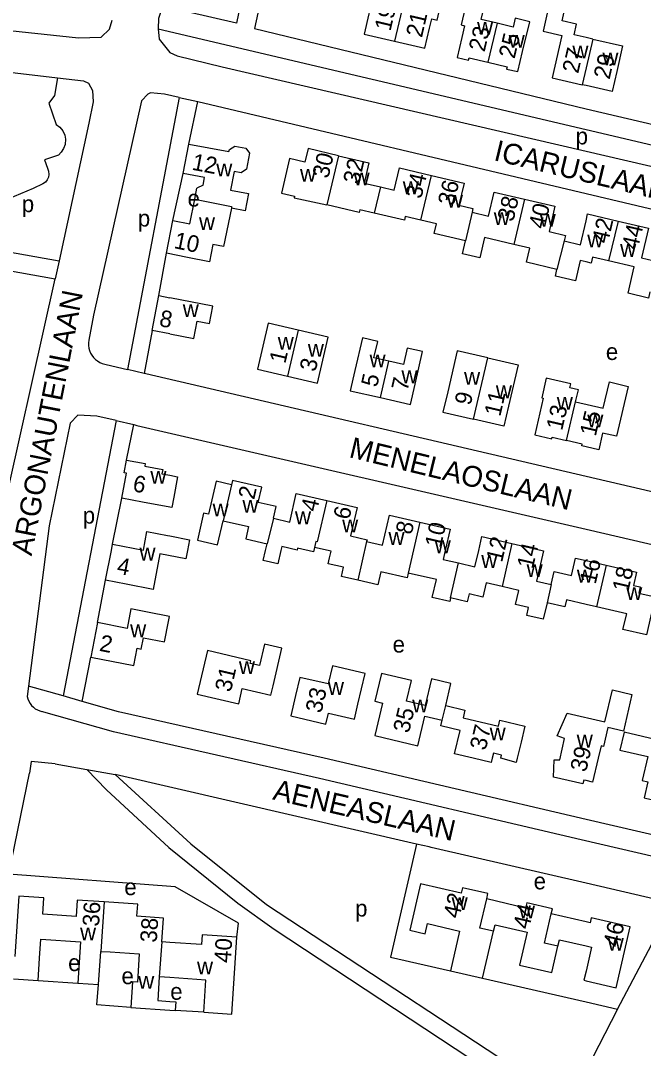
# Model space of a CAD drawing. Extents: x 161773 to 163836, y 384796 to 386521.
# Drawn here: x 162464.1 to 162613.8, y 385630.2 to 385877.5 of the extents above; entities that cross this region are included whole.
import ezdxf

# ---------------------------------------------------------------- set-up
doc = ezdxf.new("R2010")
doc.units = 0
for name, color, linetype in [('BLT_Basislijn', 7, 'Continuous'), ('BLT_Bebouwing', 7, 'Continuous'), ('BLT_Centroide', 7, 'Continuous'), ('BLT_Huisnummer', 7, 'Continuous'), ('BLT_Huisnummer_ tussenligend', 7, 'Continuous'), ('BLT_Onderverdeling_panden', 7, 'Continuous'), ('BLT_Straatnaam', 7, 'Continuous')]:
    doc.layers.add(name, color=color, linetype=linetype)

msp = doc.modelspace()

# ---------------------------------------------------------------- linework, layer by layer
at = {"layer": 'BLT_Basislijn'}
for p, q in [((162461.42, 385865.06), (162472.97, 385863.71)), ((162502.23, 385858.98), (162489.78, 385793.51)), ((162502.23, 385858.98), (162506.71, 385857.98)), ((162504.5, 385847.76), (162506.71, 385857.98)), ((162500.72, 385829.35), (162503.15, 385840.66)), ((162414.31, 385825.68), (162472.4, 385815.29)), ((162497.32, 385811.31), (162499.13, 385821.48)), ((162473.35, 385819.69), (162472.4, 385815.29)), ((162451.9, 385723.59), (162472.4, 385815.29)), ((162495.7, 385802.91), (162493.82, 385792.55)), ((162484.66, 385794.72), (162489.78, 385793.51)), ((162493.82, 385792.55), (162489.78, 385793.51)), ((162487.07, 385781.24), (162474.31, 385715)), ((162487.07, 385781.24), (162491.31, 385780.26)), ((162489.56, 385771.74), (162491.31, 385780.26)), ((162486.21, 385751.53), (162488.44, 385762.56)), ((162482.6, 385732.63), (162484.53, 385742.82)), ((162478.88, 385713.69), (162480.99, 385724.31)), ((162466.02, 385717.38), (162465.7, 385714.88)), ((162474.31, 385715), (162466.02, 385717.38)), ((162478.88, 385713.69), (162474.31, 385715)), ((162466.61, 385699.21), (162466.25, 385696.44)), ((162472.41, 385698.7), (162466.61, 385699.21)), ((162472.41, 385698.7), (162480.03, 385697.29)), ((162480.03, 385697.29), (162486.81, 385696.07)), ((162461.27, 385672.1), (162466.25, 385696.44)), ((162559.29, 385679.37), (162486.81, 385696.07)), ((162560.79, 385679.02), (162559.29, 385679.37)), ((162562.34, 385678.67), (162560.79, 385679.02)), ((162468.3, 385646.56), (162477.83, 385645.91)), ((162508.14, 385638.94), (162501.24, 385639.38))]:
    msp.add_line(p, q, dxfattribs=at)
for points in [[(162529.37, 385941.22), (162515.97, 385876.86), (162498.2, 385880.88)], [(162312.67, 385896.24), (162312.77, 385894.67), (162313.69, 385892.54), (162317.19, 385890.56), (162477.99, 385873.28), (162483.44, 385873.42), (162485.48, 385875.36), (162486.1, 385877.57)], [(162498.2, 385880.88), (162497.24, 385877.94), (162497.15, 385875.44)], [(162521.74, 385882.16), (162520.32, 385875.52), (162600, 385856.24), (162711.04, 385830.23)], [(162497.15, 385875.44), (162497.39, 385872.99), (162499.99, 385869.75), (162501.74, 385869), (162512.55, 385866.3), (162600, 385846.01), (162705.04, 385821.65), (162706.25, 385821.76), (162708.69, 385825.93)], [(162497.15, 385875.44), (162600, 385851.25), (162686.26, 385830.96), (162708.69, 385825.93)], [(162425.24, 385869.19), (162421.12, 385828.99), (162473.35, 385819.69)], [(162472.97, 385863.71), (162472.22, 385859.43), (162470.92, 385857.59), (162472.66, 385852.48), (162473.55, 385851.82), (162474.24, 385850.96), (162474.71, 385849.92), (162474.9, 385848.93), (162474.8, 385847.64), (162474.44, 385846.64), (162473.85, 385845.76), (162473.17, 385845.11), (162469.82, 385843.97), (162470.52, 385841.91), (162470.8, 385841.23), (162470.89, 385840.42), (162470.78, 385839.8), (162470.48, 385839.13), (162470.05, 385838.6), (162469.42, 385838.16), (162467.14, 385837.07), (162459.5, 385833.85)], [(162472.97, 385863.71), (162479.21, 385862.98), (162480.38, 385862.38), (162481.41, 385860.63), (162481.51, 385857.94), (162480.53, 385852.8), (162473.35, 385819.69)], [(162502.23, 385858.98), (162498.71, 385859.75), (162495.28, 385860.05), (162494.64, 385859.77), (162493.14, 385858.11), (162481.65, 385806.62), (162480.46, 385800.6)], [(162506.71, 385857.98), (162600, 385835.85), (162640.95, 385826.14), (162696.67, 385813.29), (162698.68, 385810.91), (162698.59, 385809.21), (162697.98, 385807.33), (162695.51, 385802.74), (162670.9, 385757.98), (162668.34, 385753.87), (162666.97, 385753.1), (162663.98, 385752.9), (162600, 385767.81), (162494.17, 385792.47), (162493.82, 385792.55)], [(162480.46, 385800.6), (162480.4, 385799.96), (162480.41, 385799.32), (162480.5, 385798.69), (162480.68, 385798.07), (162480.93, 385797.48), (162481.24, 385796.93), (162481.63, 385796.42), (162482.08, 385795.96), (162482.58, 385795.57), (162483.12, 385795.23), (162483.71, 385794.97), (162484.32, 385794.79), (162484.66, 385794.72)], [(162487.07, 385781.24), (162482.43, 385782.28), (162477.87, 385782.53), (162476.02, 385780.59), (162470.93, 385755.93), (162466.02, 385717.38)], [(162491.31, 385780.26), (162492.03, 385780.09), (162600, 385755.09), (162650.39, 385743.43), (162656.88, 385741.42), (162658.73, 385739.77), (162658.98, 385738.52), (162658.89, 385736.42), (162645.84, 385711.4), (162639.64, 385700), (162630.76, 385683.64)], [(162465.7, 385714.88), (162465.85, 385714.29), (162466.07, 385713.73), (162466.37, 385713.21), (162466.73, 385712.73), (162467.16, 385712.3), (162467.63, 385711.94), (162468.15, 385711.64), (162468.71, 385711.41), (162469.09, 385711.3)], [(162627.38, 385678.91), (162600, 385685.3), (162537.03, 385700), (162487.65, 385711.18), (162478.88, 385713.69)], [(162621.27, 385675.2), (162598.86, 385680.43), (162535.91, 385695.13), (162486.41, 385706.33), (162469.09, 385711.3)], [(162480.03, 385697.29), (162484.76, 385692.41), (162499.73, 385678.57), (162516.28, 385665.15), (162525.02, 385658.94), (162593.93, 385613.48)], [(162486.81, 385696.07), (162505.04, 385679.47), (162523.2, 385664.83), (162595.86, 385617.08)], [(162559.29, 385679.37), (162553.03, 385652.18), (162567.4, 385648.92)], [(162607.61, 385639.65), (162618.82, 385660.94), (162619.18, 385663.66), (162617.56, 385665.85), (162600, 385669.93), (162562.75, 385678.57), (162562.34, 385678.67)], [(162516.1, 385656.99), (162516.47, 385660.37), (162501.21, 385669.05), (162461.27, 385672.1)], [(162490.56, 385640.09), (162482.41, 385640.73), (162482.81, 385645.58)], [(162575.15, 385647.11), (162600, 385641.4), (162607.61, 385639.65)], [(162607.61, 385639.65), (162600, 385625.03), (162595.86, 385617.08)]]:
    msp.add_lwpolyline(points, dxfattribs=at)
at = {"layer": 'BLT_Bebouwing'}
for p, q in [((162503.15, 385840.66), (162504.5, 385847.76)), ((162507.94, 385837.89), (162506.48, 385837.1)), ((162499.13, 385821.48), (162500.72, 385829.35)), ((162495.7, 385802.91), (162497.32, 385811.31)), ((162497.32, 385811.31), (162500, 385810.79)), ((162500, 385802.08), (162495.7, 385802.91)), ((162522.98, 385750), (162523.34, 385751.57)), ((162582.21, 385751.67), (162589.45, 385750)), ((162482.6, 385732.63), (162480.99, 385724.31)), ((162560.24, 385669.84), (162557.63, 385658.67)), ((162575.15, 385647.11), (162577.79, 385658.39)), ((162468.66, 385651.94), (162468.97, 385656.5)), ((162482.81, 385645.58), (162483.35, 385653.57)), ((162468.3, 385646.56), (162468.66, 385651.94)), ((162567.4, 385648.92), (162575.15, 385647.11)), ((162462.35, 385646.96), (162468.3, 385646.56)), ((162477.83, 385645.91), (162482.81, 385645.58))]:
    msp.add_line(p, q, dxfattribs=at)
for points in [[(162601.61, 385873.01), (162600, 385873.38), (162597.16, 385874.04), (162597.74, 385876.56), (162594.25, 385877.37), (162597.13, 385890.48), (162593.34, 385891.35)], [(162556.51, 385883.36), (162549.47, 385885.2), (162549.72, 385886.24), (162548.36, 385886.56), (162547.19, 385881.58), (162548.34, 385881.3), (162547.81, 385879.06), (162546.67, 385874.19), (162553.96, 385872.48)], [(162553.96, 385872.48), (162561.24, 385870.78), (162562.38, 385875.64), (162562.91, 385877.88), (162564.19, 385877.58), (162565.67, 385883.91), (162557.01, 385885.94), (162556.51, 385883.36)], [(162578.63, 385876.81), (162574.79, 385877.73), (162575.27, 385879.72), (162575.54, 385880.84), (162571.31, 385881.85), (162570.01, 385876.41), (162570.83, 385876.21), (162570.16, 385873.41), (162569, 385868.55), (162571.75, 385867.89), (162571.89, 385868.48), (162576.39, 385867.41)], [(162591.3, 385882.08), (162589.72, 385874.89), (162594.23, 385873.89), (162591.87, 385863.69), (162599.06, 385862.02)], [(162576.39, 385867.41), (162581.03, 385866.3), (162580.91, 385865.8), (162583.6, 385865.16), (162584.76, 385870.03), (162586.46, 385877.17), (162582.97, 385878), (162582.47, 385875.9), (162578.63, 385876.81)], [(162601.61, 385873.01), (162608.8, 385871.34), (162607.38, 385865.18), (162606.26, 385860.36), (162600, 385861.81), (162599.06, 385862.02)], [(162504.5, 385847.76), (162514.14, 385845.93), (162514.31, 385846.4), (162515.6, 385847.28), (162518.25, 385846.77), (162519.1, 385845.53), (162518.37, 385841.69), (162517.08, 385840.81), (162515.42, 385841.12), (162514.57, 385836.67), (162518.88, 385835.85)], [(162540.49, 385844.93), (162533.2, 385846.64), (162532.43, 385843.38), (162528.73, 385844.25), (162526.79, 385835.96), (162529.96, 385835.22), (162529.87, 385834.85), (162537.71, 385833.09)], [(162540.49, 385844.93), (162547.79, 385843.22), (162546.65, 385838.38), (162550.57, 385837.46)], [(162507.94, 385837.89), (162508.28, 385839.68), (162503.15, 385840.66)], [(162550.57, 385837.46), (162553.9, 385836.68), (162555.16, 385842.02), (162562.84, 385840.21)], [(162562.84, 385840.21), (162570.7, 385838.37), (162569.45, 385833.05), (162572.81, 385832.26), (162572.6, 385831.36)], [(162505.95, 385834.5), (162506.48, 385837.1)], [(162518.88, 385835.85), (162518.1, 385831.72), (162514.75, 385832.36)], [(162572.6, 385831.36), (162576.55, 385830.43), (162577.91, 385836.21), (162585.21, 385834.5)], [(162500.72, 385829.35), (162504.75, 385828.53), (162505.95, 385834.5)], [(162585.21, 385834.5), (162592.54, 385832.78), (162591.11, 385826.72), (162595.08, 385825.79), (162594.77, 385824.44)], [(162514.75, 385832.36), (162512.87, 385823.1), (162510.33, 385823.61), (162509.48, 385819.39), (162504.21, 385820.45), (162499.13, 385821.48)], [(162549.09, 385831.15), (162545.63, 385831.96), (162545.46, 385831.27), (162537.71, 385833.09)], [(162560.31, 385829.41), (162556.54, 385830.29), (162556.35, 385829.44), (162549.09, 385831.15)], [(162594.77, 385824.44), (162598.65, 385823.53), (162600, 385829.29), (162600.39, 385830.95), (162607.7, 385829.23)], [(162571.07, 385824.51), (162563.54, 385826.27), (162564.07, 385828.53), (162560.31, 385829.41)], [(162607.7, 385829.23), (162615, 385827.52), (162613.33, 385820.39), (162617.39, 385819.43)], [(162582.66, 385823.62), (162575.62, 385825.28), (162574.46, 385820.35), (162570.32, 385821.32), (162571.07, 385824.51)], [(162593.01, 385817.59), (162585.67, 385819.31), (162586.48, 385822.73), (162582.66, 385823.62)], [(162605.44, 385819.63), (162601.59, 385820.53), (162601.26, 385819.11), (162600, 385819.4), (162598.61, 385819.73), (162597.46, 385814.84), (162592.63, 385815.97), (162593.01, 385817.59)], [(162615.34, 385812.19), (162615, 385810.71), (162610.12, 385811.86), (162611.61, 385818.18), (162605.44, 385819.63)], [(162500, 385802.08), (162505.75, 385800.96), (162506.56, 385805.15), (162509.52, 385804.58), (162510.33, 385808.79), (162500, 385810.79)], [(162530.81, 385802.96), (162523.57, 385804.65), (162521, 385793.61), (162528.24, 385791.92)], [(162528.24, 385791.92), (162535.47, 385790.24), (162538.04, 385801.27), (162530.81, 385802.96)], [(162552.57, 385795.51), (162549.03, 385796.32), (162549.93, 385800.28), (162546.24, 385801.12), (162544.46, 385793.29), (162543.35, 385788.42), (162550.58, 385786.77)], [(162550.58, 385786.77), (162557.81, 385785.13), (162558.92, 385790.01), (162560.7, 385797.84), (162557.01, 385798.68), (162556.11, 385794.71), (162552.57, 385795.51)], [(162576.39, 385796.34), (162569.06, 385797.98), (162566.76, 385788.15), (162565.62, 385783.28), (162572.95, 385781.57)], [(162576.39, 385796.34), (162583.71, 385794.64), (162581.41, 385784.74), (162580.28, 385779.87), (162572.95, 385781.57)], [(162597.5, 385785.76), (162598.17, 385788.62), (162596.15, 385789.09), (162596.38, 385790.06), (162590.46, 385791.43), (162589.36, 385786.71), (162589.72, 385786.62), (162587.67, 385777.77), (162591.79, 385776.81), (162591.9, 385777.25), (162595.32, 385776.46)], [(162597.5, 385785.76), (162604.16, 385784.21), (162605.63, 385790.52), (162610.15, 385789.47), (162607.35, 385777.46), (162604, 385778.24), (162603.06, 385774.2), (162600, 385774.91), (162598.96, 385775.15), (162599.06, 385775.59), (162595.32, 385776.46)], [(162488.44, 385762.56), (162489.55, 385768.56), (162488.99, 385768.66), (162489.56, 385771.74)], [(162489.56, 385771.74), (162494.04, 385770.92), (162493.93, 385770.28), (162498.26, 385769.48), (162498.06, 385768.43), (162500, 385768.08)], [(162500, 385768.08), (162501.81, 385767.74), (162500.91, 385762.82), (162500.45, 385760.34), (162500, 385760.43)], [(162514.81, 385765.82), (162511.11, 385766.68), (162509.26, 385758.69), (162508.02, 385758.97), (162506.58, 385752.45), (162511.45, 385751.33), (162512.81, 385757.15)], [(162524.85, 385757.74), (162525.5, 385760.54), (162521.2, 385761.53), (162522.05, 385765.18), (162515.03, 385766.8), (162514.81, 385765.82)], [(162500, 385760.43), (162493.36, 385761.65), (162488.44, 385762.56)], [(162524.85, 385757.74), (162528.77, 385756.83), (162530.35, 385763.71), (162537.68, 385762.01)], [(162537.68, 385762.01), (162545, 385760.32), (162543.42, 385753.48), (162547.37, 385752.56), (162547.27, 385752.13)], [(162512.81, 385757.15), (162518.9, 385755.74), (162518.21, 385752.76), (162523.34, 385751.57)], [(162547.27, 385752.13), (162551.12, 385751.24), (162552.78, 385758.47), (162560.06, 385756.79)], [(162560.06, 385756.79), (162567.33, 385755.11), (162566.15, 385750)], [(162486.21, 385751.53), (162493.61, 385750.1), (162494.47, 385754.55), (162499.38, 385753.6), (162500, 385753.48)], [(162484.53, 385742.82), (162485.92, 385750), (162486.21, 385751.53)], [(162500, 385753.48), (162504.68, 385752.58), (162504.18, 385750)], [(162574.2, 385750), (162574.97, 385753.34), (162582.21, 385751.67)], [(162504.18, 385750), (162503.79, 385747.96), (162497.59, 385749.16), (162495.94, 385740.62), (162489.44, 385741.87), (162484.53, 385742.82)], [(162526.68, 385750), (162525.93, 385746.76), (162522.42, 385747.57), (162522.98, 385750)], [(162534.74, 385750.71), (162534.51, 385749.68), (162530.68, 385750.56), (162530.57, 385750.06), (162526.89, 385750.91), (162526.68, 385750)], [(162538.72, 385749.79), (162534.74, 385750.71)], [(162545.14, 385742.86), (162541.23, 385743.76), (162541.74, 385745.95), (162538.03, 385746.8), (162538.36, 385748.25), (162538.72, 385749.79)], [(162566.15, 385750), (162565.65, 385747.84), (162569.38, 385746.98)], [(162569.38, 385746.98), (162573.3, 385746.08), (162574.2, 385750)], [(162589.45, 385750), (162589.77, 385749.92), (162588.09, 385742.63), (162591.65, 385741.81)], [(162591.65, 385741.81), (162592.37, 385744.9), (162596.54, 385743.94), (162597.51, 385748.17), (162600, 385747.6), (162604.82, 385746.48)], [(162557.24, 385744.56), (162556.98, 385743.44), (162550.68, 385744.89), (162549.96, 385741.75), (162545.14, 385742.86)], [(162567.45, 385738.6), (162567.24, 385737.71), (162563.04, 385738.68), (162564.03, 385742.99), (162557.24, 385744.56)], [(162604.82, 385746.48), (162612.13, 385744.8), (162611.39, 385741.6), (162613.03, 385741.23), (162612.69, 385739.76), (162616.63, 385738.85), (162614.52, 385729.71), (162608.87, 385731.02), (162609.8, 385734.73), (162602.5, 385736.42)], [(162579.82, 385741.3), (162575.97, 385742.19), (162575.18, 385738.78), (162571.89, 385739.54), (162571.46, 385737.67), (162567.45, 385738.6)], [(162590.66, 385737.42), (162589.74, 385733.44), (162585.75, 385734.36), (162586.19, 385736.25), (162583.06, 385736.97), (162583.85, 385740.37), (162579.82, 385741.3)], [(162602.5, 385736.42), (162600, 385736.99), (162595.29, 385738.08), (162594.91, 385736.44), (162590.66, 385737.42)], [(162480.99, 385724.31), (162491.35, 385722.31), (162492.15, 385726.47), (162493.11, 385726.28), (162493.63, 385728.99), (162498.71, 385728.01), (162499.66, 385732.92), (162499.89, 385734.14), (162494.6, 385735.16), (162490.58, 385735.94), (162489.67, 385731.26), (162482.6, 385732.63)], [(162524.25, 385715.19), (162524.33, 385715.53), (162524.77, 385717.41), (162526.88, 385726.51), (162522.73, 385727.47), (162521.52, 385722.29), (162519.27, 385722.82), (162519.43, 385723.47), (162508.98, 385725.9), (162506.55, 385715.44), (162516.52, 385713.12), (162517.37, 385716.79), (162524.25, 385715.19)], [(162544.33, 385709.39), (162545.17, 385713.04), (162546.88, 385720.44), (162539.07, 385722.25), (162538.06, 385717.89), (162531.22, 385719.47), (162530.2, 385715.07), (162529.07, 385710.19), (162537.47, 385708.25), (162538.07, 385710.84), (162544.33, 385709.39)], [(162566.28, 385712.71), (162567.52, 385717.99), (162562.84, 385719.09), (162561.34, 385712.68), (162556.86, 385713.73), (162558.04, 385718.75), (162550.84, 385720.44), (162549.26, 385713.71), (162551.07, 385713.28), (162549.23, 385705.46), (162559.55, 385703.04)], [(162604.55, 385708.74), (162606.37, 385716.46), (162611.04, 385715.36), (162608.98, 385706.55), (162605.26, 385707.41), (162604.21, 385702.86), (162603.61, 385703), (162602.92, 385700), (162601.59, 385694.27), (162600, 385694.64), (162599.47, 385694.76), (162599.26, 385693.86), (162592.2, 385695.49), (162592.32, 385699.61), (162593.68, 385699.61), (162594.87, 385704.74), (162593.05, 385705.43), (162595.47, 385710.83), (162604.55, 385708.74)], [(162566.28, 385712.71), (162570.89, 385711.62), (162570.45, 385709.72), (162578.94, 385707.71), (162579.28, 385709.15), (162585.31, 385707.73), (162584.39, 385703.86)], [(162559.55, 385703.04), (162561.22, 385710.17), (162565.45, 385709.17)], [(162584.39, 385703.86), (162583.48, 385700), (162583.24, 385698.99), (162579.55, 385700), (162579.72, 385700.73), (162577.74, 385701.2), (162577.46, 385700), (162577.22, 385698.97), (162572.86, 385700), (162568.4, 385701.05), (162569.73, 385706.7), (162565.12, 385707.78), (162565.45, 385709.17)], [(162621.1, 385698.16), (162621.89, 385701.47), (162617.58, 385702.5), (162617.98, 385704.2), (162609.15, 385706.31), (162608.11, 385701.96), (162614.84, 385700.41), (162613.51, 385694.63), (162614.9, 385694.31), (162613.96, 385690.49), (162625.12, 385687.84), (162627.23, 385696.7), (162621.1, 385698.16)], [(162576.14, 385666.17), (162576.44, 385667.45), (162570.31, 385668.88), (162570, 385667.56), (162560.24, 385669.84)], [(162469.45, 385662.51), (162469.71, 385666.45), (162463.69, 385666.86), (162462.71, 385652.34)], [(162484.15, 385665.48), (162477.7, 385665.92), (162477.44, 385661.97), (162469.45, 385662.51)], [(162498.02, 385655.85), (162498.41, 385661.59), (162492.07, 385662.01), (162492.27, 385664.94), (162484.15, 385665.48)], [(162591.65, 385662.59), (162591.94, 385663.83), (162585.78, 385665.27), (162585.48, 385663.99), (162576.14, 385666.17)], [(162593.25, 385654.78), (162593.63, 385656.36), (162600, 385654.87), (162601.34, 385654.55), (162600, 385648.84), (162599.48, 385646.63), (162600, 385646.51), (162607.22, 385644.82), (162610.65, 385659.48), (162601.27, 385661.67), (162600.98, 385660.41), (162600, 385660.63), (162591.65, 385662.59)], [(162557.63, 385658.67), (162561.35, 385657.8), (162561.92, 385660.23), (162569.63, 385658.43), (162567.4, 385648.92)], [(162577.79, 385658.39), (162578.16, 385659.96), (162585.86, 385658.16), (162584.01, 385650.27), (162591.78, 385648.45), (162593.25, 385654.78)], [(162468.97, 385656.5), (162478.49, 385655.87), (162477.83, 385645.91)], [(162516.1, 385656.99), (162507.74, 385657.55), (162507.58, 385655.2), (162500, 385655.71), (162498.02, 385655.85)], [(162508.14, 385638.94), (162514.86, 385638.49), (162515.76, 385652), (162516.1, 385656.99)], [(162483.35, 385653.57), (162485.63, 385653.42), (162492.61, 385652.96), (162492.16, 385646.16), (162490.97, 385646.24), (162490.56, 385640.09)], [(162497.44, 385647.41), (162497.06, 385641.71), (162500, 385641.51), (162501.37, 385641.42), (162501.24, 385639.38)], [(162508.14, 385638.94), (162508.65, 385646.66), (162500, 385647.24), (162497.44, 385647.41)], [(162490.56, 385640.09), (162500, 385639.46), (162501.24, 385639.38)]]:
    msp.add_lwpolyline(points, dxfattribs=at)
at = {"layer": 'BLT_Onderverdeling_panden'}
for p, q in [((162556.51, 385883.36), (162553.96, 385872.48)), ((162578.63, 385876.81), (162576.39, 385867.41)), ((162601.61, 385873.01), (162600, 385866.06)), ((162600, 385866.06), (162599.06, 385862.02)), ((162540.49, 385844.93), (162537.71, 385833.09)), ((162560.31, 385829.41), (162562.84, 385840.21)), ((162550.57, 385837.46), (162549.09, 385831.15)), ((162585.21, 385834.5), (162582.66, 385823.62)), ((162572.6, 385831.36), (162571.07, 385824.51)), ((162607.7, 385829.23), (162605.44, 385819.63)), ((162594.77, 385824.44), (162593.01, 385817.59)), ((162530.81, 385802.96), (162528.24, 385791.92)), ((162572.95, 385781.57), (162576.39, 385796.34)), ((162550.58, 385786.77), (162552.57, 385795.51)), ((162595.32, 385776.46), (162597.5, 385785.76)), ((162514.81, 385765.82), (162512.81, 385757.15)), ((162524.85, 385757.74), (162523.34, 385751.57)), ((162560.06, 385756.79), (162557.24, 385744.56)), ((162547.27, 385752.13), (162545.14, 385742.86)), ((162582.21, 385751.67), (162579.82, 385741.3)), ((162567.45, 385738.6), (162569.38, 385746.98)), ((162604.82, 385746.48), (162602.5, 385736.42)), ((162591.65, 385741.81), (162590.66, 385737.42)), ((162565.45, 385709.17), (162566.28, 385712.71)), ((162484.15, 385665.48), (162483.35, 385653.57)), ((162498.02, 385655.85), (162497.44, 385647.41))]:
    msp.add_line(p, q, dxfattribs=at)
for points in [[(162505.95, 385834.5), (162514.82, 385832.72), (162514.75, 385832.36)], [(162537.68, 385762.01), (162535.39, 385752.07), (162535.08, 385752.15), (162534.74, 385750.71)], [(162577.79, 385658.39), (162574.49, 385659.16), (162576.14, 385666.17)], [(162593.25, 385654.78), (162590.01, 385655.53), (162591.65, 385662.59)]]:
    msp.add_lwpolyline(points, dxfattribs=at)

# ---------------------------------------------------------------- texts
at = {"layer": 'BLT_Centroide'}
for s, p in [('w', (162573.81, 385874.05)), ('w', (162581.42, 385870.92)), ('w', (162596.73, 385868.34)), ('w', (162603.94, 385866.69)), ('p', (162597.51, 385847.66)), ('w', (162511.12, 385839.98)), ('w', (162531.25, 385838.69)), ('w', (162544.14, 385837.81)), ('w', (162555.97, 385835.67)), ('e', (162504.23, 385832.71)), ('p', (162464.38, 385831.37)), ('w', (162566.56, 385832.45)), ('p', (162492.27, 385827.9)), ('w', (162577.83, 385828.28)), ('w', (162588.88, 385827.89)), ('w', (162506.97, 385827.09)), ('w', (162600.29, 385822.91)), ('w', (162608.2, 385820.62)), ('w', (162503.07, 385806.12)), ('w', (162525.91, 385798.28)), ('w', (162533.14, 385796.59)), ('e', (162604.77, 385795.81)), ('w', (162547.97, 385794.05)), ('w', (162555.64, 385790.22)), ('w', (162570.69, 385789.84)), ('w', (162578.33, 385786.62)), ('w', (162592.98, 385783.84)), ('w', (162600.31, 385779.58)), ('w', (162495.29, 385766.03)), ('w', (162517.41, 385759.06)), ('p', (162479.03, 385756.45)), ('w', (162510.24, 385758.2)), ('w', (162530.05, 385756.3)), ('w', (162541.38, 385754.36)), ('w', (162552.52, 385751.33)), ('w', (162563.64, 385749.34)), ('w', (162492.66, 385747.56)), ('w', (162574.83, 385745.8)), ('w', (162585.73, 385743.59)), ('w', (162597.81, 385742.28)), ('w', (162609.67, 385738.09)), ('w', (162490.42, 385729.12)), ('e', (162553.52, 385725.43)), ('w', (162516.56, 385720.28)), ('w', (162537.96, 385715.25)), ('w', (162558.22, 385711.06)), ('w', (162576.84, 385704.34)), ('w', (162597.77, 385702.59)), ('e', (162489.02, 385667.08)), ('e', (162587.42, 385668.48)), ('p', (162544.5, 385661.94)), ('w', (162567.7, 385663.48)), ('w', (162583.88, 385661.5)), ('w', (162478.38, 385656.22)), ('w', (162605.22, 385653.72)), ('e', (162475.52, 385648.83)), ('w', (162506.49, 385648.03)), ('e', (162488.34, 385645.68)), ('w', (162492.36, 385644.56)), ('e', (162500.06, 385641.93))]:
    msp.add_text(s, height=4, dxfattribs=at).set_placement(p)
at = {"layer": 'BLT_Huisnummer'}
for s, rotation, p in [('19', 76.8155, (162552.99, 385874.75)), ('21', 76.819, (162560.55, 385873.2)), ('23', 76.5902, (162575.61, 385869.75)), ('25', 76.592, (162582.82, 385868.11)), ('27', 76.9445, (162598.11, 385864.56)), ('29', 76.9483, (162605.65, 385863.14)), ('30', 76.7929, (162538.05, 385839.31)), ('12', 349.206, (162505.08, 385841.6)), ('34', 76.7887, (162560.41, 385834.43)), ('38', 76.7924, (162582.51, 385828.91)), ('42', 76.7951, (162605.25, 385823.63)), ('10', 348.5686, (162500.77, 385822.74)), ('8', 349.0439, (162497.23, 385804)), ('1', 76.8837, (162527.71, 385794.78)), ('3', 76.8849, (162534.98, 385792.81)), ('5', 77.1793, (162549.76, 385789.1)), ('7', 77.1866, (162557.05, 385788.18)), ('9', 76.896, (162572.24, 385784.73)), ('11', 76.9281, (162579.38, 385782.06)), ('13', 76.9006, (162594.25, 385778.67)), ('15', 76.9091, (162602.33, 385777.28)), ('6', 349.5507, (162490.86, 385764.27)), ('2', 77.0203, (162520.23, 385762.07)), ('6', 77.0097, (162543.08, 385757.22)), ('10', 77.0209, (162565.08, 385750.46)), ('14', 77.0105, (162587.22, 385745.4)), ('4', 349.0833, (162487.05, 385744.49)), ('18', 77.0088, (162610.14, 385739.8)), ('2', 349.0597, (162482.84, 385725.88)), ('31', 76.8975, (162514.61, 385715.75)), ('33', 76.9958, (162536.38, 385710.7)), ('35', 76.7761, (162557.44, 385705.9)), ('37', 76.7355, (162575.88, 385701.74)), ('39', 76.9893, (162600.02, 385696.53)), ('42', 76.8347, (162569.52, 385661.29)), ('36', 86.1601, (162482.93, 385659.46)), ('46', 76.8334, (162607.93, 385654.33)), ('40', 86.1673, (162514.59, 385650.69))]:
    msp.add_text(s, height=4, rotation=rotation, dxfattribs=at).set_placement(p)
at = {"layer": 'BLT_Huisnummer_ tussenligend'}
for s, rotation, p in [('32', 76.7868, (162545.42, 385837.92)), ('36', 76.7997, (162568.2, 385832.74)), ('40', 76.8006, (162590.03, 385827.15)), ('44', 76.7848, (162612.42, 385822.14)), ('4', 77.0155, (162535.28, 385759.12)), ('8', 77.0108, (162558.06, 385753.64)), ('12', 77.0139, (162579.82, 385746.97)), ('16', 77.0129, (162602.3, 385741.71)), ('44', 76.8302, (162586.31, 385658.7)), ('38', 86.1647, (162496.8, 385655.6))]:
    msp.add_text(s, height=4, rotation=rotation, dxfattribs=at).set_placement(p)
at = {"layer": 'BLT_Straatnaam'}
for s, height, rotation, p in [('ICARUSLAAN', 5, 346.5043, (162577.62, 385843.91)), ('ARGONAUTENLAAN', 5, 78.9636, (162466.74, 385748.55)), ('MENELAOSLAAN', 4.9999, 346.4415, (162542.83, 385772.45)), ('AENEASLAAN', 5, 346.9615, (162524.48, 385690.14))]:
    msp.add_text(s, height=height, rotation=rotation, dxfattribs=at).set_placement(p)

doc.saveas('drawing.dxf')
